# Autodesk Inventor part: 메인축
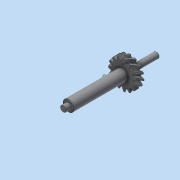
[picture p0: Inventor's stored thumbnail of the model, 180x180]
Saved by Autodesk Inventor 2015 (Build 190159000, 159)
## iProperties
Created: 2016-12
Part Number: 메인축
Material: 강철, 탄소
Document SubType Name: Modeling
Designer: mduedu
Categories: <?xml version="1.0" encoding="UTF-16"?> <MemberInstance><Categories><FamilyTemplate><FamilyTemplateParameter ValueType="xs:double" Id="1" ObjectReferenceKey="da
Density: 7.87 g/cm^3
Mass: 199.413 g
Surface Area: 86.9451 cm^2
Volume: 25.3383 cm^3
Appearance: 기본값
CustomPartVersion: 1
Author: mduedu
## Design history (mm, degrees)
sketch "Sketch1"
  geometry: C1 r 19.321 at (0, 0)
  constraints: 1 centre point
  dimensions: "d0" = 38.64102 diameter of C1 (= da_da)
extrude "Extrusion1" new body sketch "Sketch1" distance "d1" = 10 (= da_b); taper "d2" = 0 deg
workplane "Work Plane2"
sketch "Sketch2"
  geometry: C1 r 19.321 at (0, 0) reference; C2 r 17.321 at (0, 0)
  constraints: 1 centre point, 1 coincident
  dimensions: "d3" = 34.64102 diameter of C2 (= da_dw)
feature "피치 지름" sketch "Sketch2" dims "d4" = 10, "d5" = 0
workplane "Work Plane8"
workplane "Work Plane9"
feature "스퍼 기어" dims "da_b" = 10, "da_d" = 34.64102, "da_aw" = 43.87862, "da_da" = 38.64102, "da_df" = 29.64102, "da_dw" = 34.64102, angle "da_beta" = 30 deg, "da_lefttooth" = 0, "da_righttooth" = 10
sketch "스케치3"
  geometry: C1 r 7.5 at (0, 0); 1 further point
  constraints: 1 centre point, 1 coincident
  dimensions: "d49" = 15 diameter of C1
extrude "돌출2" join sketch "스케치3" distance "d50" = 74; taper "d51" = 0 deg
sketch "스케치4"
  geometry: C1 r 4 at (0, 0); 1 further point
  constraints: 1 centre point, 1 coincident
  dimensions: "d52" = 8 diameter of C1
extrude "돌출3" join sketch "스케치4" distance "d53" = 7; taper "d54" = 0 deg
sketch "스케치5"
  geometry: C1 r 7.5 at (0, 0) reference; 1 further point
extrude "돌출4" join sketch "스케치5" distance "d55" = 6; taper "d56" = 0 deg
sketch "스케치6"
  geometry: C1 r 4 at (0, 0); 1 further point
  constraints: 1 centre point, 1 coincident
  dimensions: "d57" = 8 diameter of C1
extrude "돌출5" join sketch "스케치6" distance "d58" = 30; taper "d59" = 0 deg
chamfer "모따기1" distance "d60" = 0.5; stored, may be unused: second distance "d61" = 2, angle "d62" = 45 deg
fillet "모깎기1" dims "d63" = 0.5
sketch "스케치7" dims "d64" = 25
  geometry: C1 r 1 at (0, 12.5); 2 further points
  constraints: 2 vertical alignment, 1 centre point, 1 coincident, 2 other
  dimensions: "d65" = 2 diameter of C1
extrude "돌출6" join sketch "스케치7" distance "d66" = 0.5; taper "d67" = 0 deg
sketch "스케치8"
  geometry: L1 (0, 0)-(69.675, -61.749); C1 r 3.5 at (0, 0) reference; C2 r 3.5 at (69.675, -61.749) reference
  constraints: 2 end point
  node "참조1"
body "Solid1"
body "Srf1"
other parameters: "d16" = 43.87862 (= da_aw), "d17" = 0, "d34" = 12 deg (computed from da_z), "d39" = 0, "d41" = 0, "d43" = 43.87862 (= da_aw), "d46" = 43.87862 (= da_aw), "d47" = 0, "d48" = 0
